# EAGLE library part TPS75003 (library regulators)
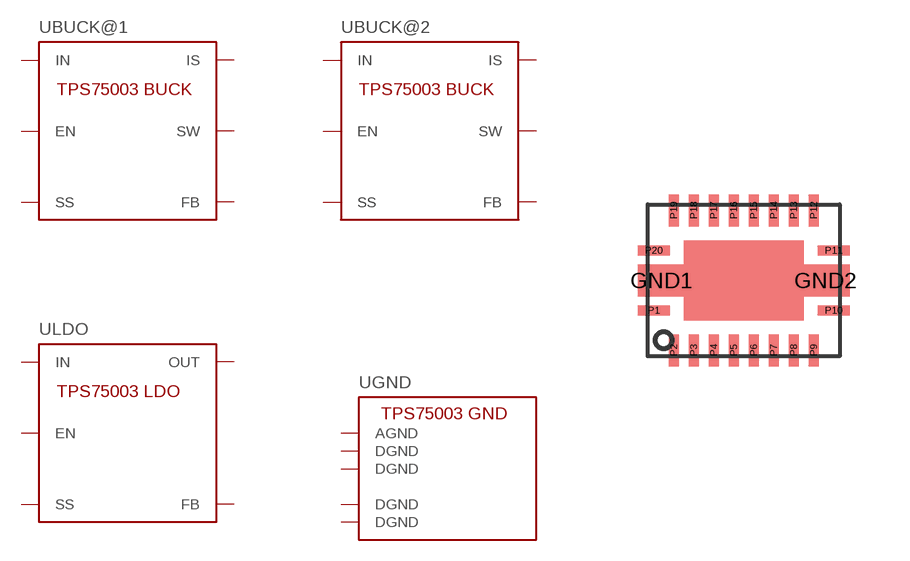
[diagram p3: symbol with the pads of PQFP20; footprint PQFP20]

Designator prefix U; gates BUCK@1=TPS75003-BUCK BUCK@2=TPS75003-BUCK LDO=TPS75003-LDO GND=TPS75003-GND

## TPS75003  [PQFP20]
GND1  GND:DGND  pwr
GND2  GND:DGND  pwr
P1  LDO:OUT  pwr
P2  LDO:FB  in
P3  LDO:EN  in
P4  BUCK@2:EN  in
P5  BUCK@2:SS  in
P6  GND:DGND  pwr
P7  BUCK@2:SW  out
P8  BUCK@2:IN  pwr
P9  BUCK@2:IS  in
P10  BUCK@2:FB  in
P11  BUCK@1:FB  in
P12  BUCK@1:IS  in
P13  BUCK@1:IN  pwr
P14  BUCK@1:SW  out
P15  GND:DGND  pwr
P16  BUCK@1:SS  in
P17  BUCK@1:EN  in
P18  GND:AGND  pwr
P19  LDO:SS  in
P20  LDO:IN  pwr

## Footprint PQFP20 (pad centres in mm)
smd 1.2 x 0.8: GND1 -2.05,0; GND2 2.05,0
smd 0.8 x 0.25: P1 -2.25,-0.75; P10 2.25,-0.75; P11 2.25,0.75; P20 -2.25,0.75
smd 0.25 x 0.8: P2 -1.75,-1.75; P3 -1.25,-1.75; P4 -0.75,-1.75; P5 -0.25,-1.75; P6 0.25,-1.75; P7 0.75,-1.75; P8 1.25,-1.75; P9 1.75,-1.75; P12 1.75,1.75; P13 1.25,1.75; P14 0.75,1.75; P15 0.25,1.75; P16 -0.25,1.75; P17 -0.75,1.75; P18 -1.25,1.75; P19 -1.75,1.75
